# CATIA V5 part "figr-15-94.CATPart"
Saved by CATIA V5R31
Part number: Part1
Bounding box of the stored display mesh (mm): x -40 to 40, y -60 to 60, z -4 to 2
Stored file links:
  D:\PROJECTS\Project 2021\US EDITION\CATIA V5 6R 2021\Resources\Part Files\c15_catia_v5_6r2021_prt\figr-15-94.CATPart
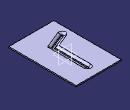
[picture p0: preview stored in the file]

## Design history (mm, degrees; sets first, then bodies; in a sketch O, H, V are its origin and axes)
SheetMetalParameters1: Thickness 2, BendRadius 4, KFactor 0.400515 {= log(min(100,max(20*SheetMetalParameters1.BendRadius,SheetMetalParameters1.Thickness)/SheetMetalParameters1.Thickness))/log(100)/2}, ReliefRadialLength 1, ReliefAxialLength 2, MinimumBendRadius 0
Body1 (main body)
  Sketch1 on xy-plane, origin (0, 0, 0), H (-1, 0, 0), V (0, -1, 0)
    line L1 (40, 60) -> (40, -60)
    line L2 (40, -60) -> (-40, -60)
    line L3 (-40, -60) -> (-40, 60)
    line L4 (-40, 60) -> (40, 60)
    length L4 = 80
    length L1 = 120
    vertical: L1 V, L3 V
    horizontal: L2 H, L4 H
    equidistance: L1 L3 O, L2 L4 O
  Wall1: Thickness 2, Profile Sketch1, OffsetValue 0
  Sketch2 on face of Wall1, origin (0, 0, 2), H (1, 0, 0), V (0, 1, 0)
    line L1 (0, 40.0798) -> (0, -21.0085)
    line L2 (0, -21.0085) -> (-27, -32)
    vertical: L1 V
  d_Stamp1: NewRoot_AttribNormalisation "No Standard", Stamp_FilletRadius 2, Stamp_IntersectFilletRadius 2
